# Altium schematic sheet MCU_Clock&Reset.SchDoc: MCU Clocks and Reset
size A4; Date: Not used; ApprovedBy: Not used; CheckedBy: Not used; Author: Not used; CompanyName: STMicroelectronics; DrawnBy: Not used; Engineer: Not used; Organization: Not used; Address1: Not used; Address2: Not used; Address3: Not used; Address4: Not used; DocumentNumber: Not used; Revision: Not used; SheetNumber: 4; SheetTotal: 23
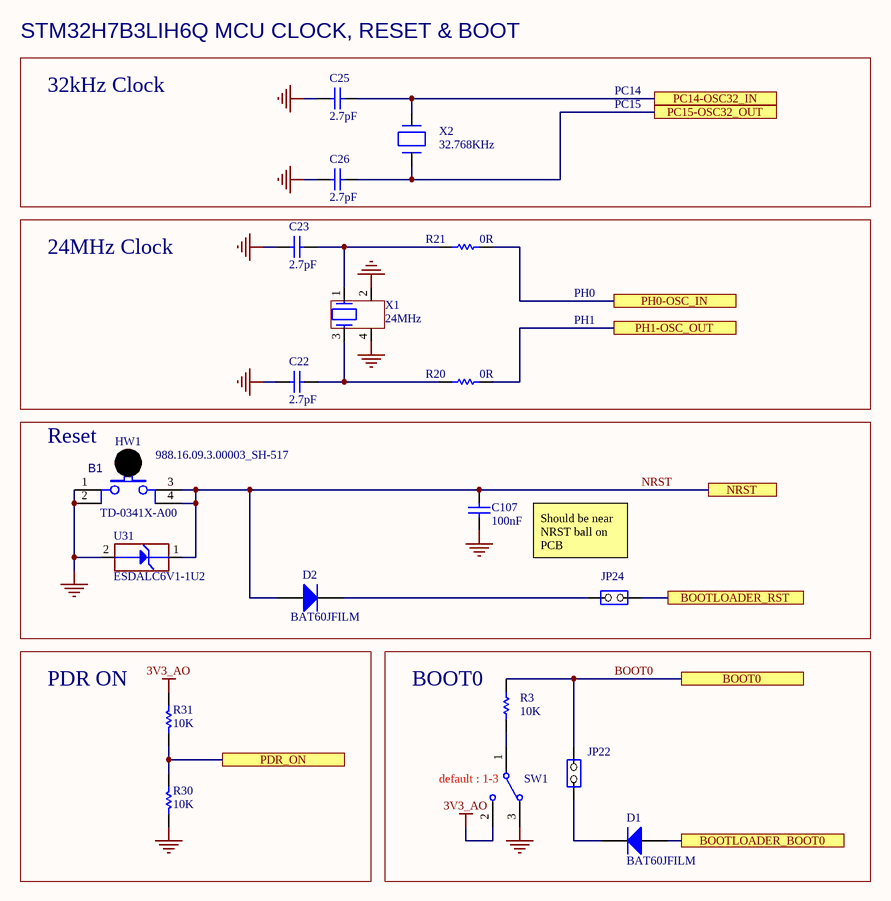
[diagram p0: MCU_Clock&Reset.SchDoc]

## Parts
B1  value TD-0341X-A00  [SWI_WEALTHMETAL_TD-0341_4P_BLACK]  (hidden comment: SW-PUSH-CMS)
C22  value 2.7pF  [C0603]  (hidden comment: Capacitor)
C23  value 2.7pF  [C0603]  (hidden comment: Capacitor)
C25  value 2.7pF  [C0603]  (hidden comment: Capacitor)
C26  value 2.7pF  [C0603]  (hidden comment: Capacitor)
C107  value 100nF  [C0402]  (hidden comment: Capacitor)
D1  BAT60JFILM  [DIO_SOD323]
D2  BAT60JFILM  [DIO_SOD323]
HW1  value 988.16.09.3.00003_SH-517  (hidden comment: BUTTON_HAT_BLACK)  (mechanical)
JP22  Jumper_Header 2x1  [CON_SAMTEC_TSW-102-07-G-S]  (value not drawn)
JP24  Jumper_Header 2x1  [CON_SAMTEC_TSW-102-07-G-S]  (value not drawn)
R3  value 10K  [R0402]  (hidden comment: Resistor)
R20  value 0R  [R0402]  (hidden comment: Resistor)
R21  value 0R  [R0402]  (hidden comment: Resistor)
R30  value 10K  [R0402]  (hidden comment: Resistor)
R31  value 10K  [R0402]  (hidden comment: Resistor)
SW1  SW_MECA_1K2  [SWI_EAO_09-03290-01_EXTENDED_STRAIGHT_BLACK]  (value not drawn)
U31  value ESDALC6V1-1U2  [ESD_ST0201]  (hidden comment: ESD-TRANSIL)
X1  value 24MHz  [CRY_NX2016SA_4P]  (hidden comment: XTAL_4_PINS)
X2  value 32.768KHz  [CRY_NX3215SA_2P]  (hidden comment: XTAL_2_PINS)

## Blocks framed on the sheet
24MHz Clock: C22 C23 R20 R21 X1
Reset: B1 C107 D2 HW1 JP24 U31
PDR ON: R30 R31
BOOT0: D1 JP22 R3 SW1

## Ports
BOOT0, BOOTLOADER_BOOT0, BOOTLOADER_RST, NRST, PC14-OSC32_IN, PC15-OSC32_OUT, PDR_ON, PH0-OSC_IN, PH1-OSC_OUT

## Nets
3V3_AO: R31.1 SW1.2
GND: B1.1 B1.2 C22.1 C23.1 C25.1 C26.1 C107.1 R30.2 SW1.3 U31.2(GND) X1.2 X1.4
BOOT0: JP22.2(NO) R3.1 ; port BOOT0
BOOTLOADER_BOOT0: D1.1(A) ; port BOOTLOADER_BOOT0
BOOTLOADER_RST: JP24.2(NO) ; port BOOTLOADER_RST
NRST: B1.3 B1.4 C107.2 D2.1(A) U31.1(IO1) ; port NRST
PC14-OSC32_IN: C25.2 X2.2(X2) ; port PC14-OSC32_IN
PC15-OSC32_OUT: C26.2 X2.1(X1) ; port PC15-OSC32_OUT
PDR_ON: R30.1 R31.2 ; port PDR_ON
PH0-OSC_IN: R21.2 ; port PH0-OSC_IN
PH1-OSC_OUT: R20.2 ; port PH1-OSC_OUT
NetC22_2: C22.2 R20.1 X1.3
NetC23_2: C23.2 R21.1 X1.1
NetD1_2: D1.2(K) JP22.1(COMMON)
NetD2_2: D2.2(K) JP24.1(COMMON)
NetR3_2: R3.2 SW1.1

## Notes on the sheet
- STM32H7B3LIH6Q MCU CLOCK, RESET & BOOT
- 32kHz Clock
- PC14
- PC15
- PH0
- PH1
- Should be near NRST ball on PCB
- (near SW1) default : 1-3

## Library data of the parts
B1 = MCD-00001: Non-Open Push-Button 0.1A 24V BLACK; Manufacturer: WEALTHMETAL; Part_Type: Misc; Part_Preference: Not recommended; Partial_Alternate_Internal_Part_Number: MCD-03587; Provided_By: SUBCO; Alternate_EMS: A; Component_Country_Of_Origin: Unknown; ID: 2463; ShowFields: YES
C22 C23 C25 C26 = MCD-01726: Capacitor, MLCC, 2.7pF, 50V, NPO, -+0.25pF 0603; Manufacturer_Part_Number: CC0603CRNPO9BN2R7; Manufacturer: YAGEO; Part_Preference: Recommended; Provided_By: SUBCO; Component_Country_Of_Origin: China; ID: 3826; Order_Code_RS: 616-9155; ShowFields: YES
C107 = MCD-00006: Capacitor, MLCC, 100nF, 16V, X7R, 10%, 0402, T=0.5mm; Manufacturer_Part_Number: CC0402KRX7R7BB104; Manufacturer: YAGEO; Alternate_Manufacturer_Part_Number: GCM155R71C104KA55D; Alternate_Manufacturer: MURATA; Part_Preference: Recommended; Partial_Alternate_Internal_Part_Number: MCD-03299; Provided_By: SUBCO; ECCN_US: EAR99; ECCN_EU: NEC; Component_Country_Of_Origin: China; ID: 2474; Order_Code_RS: 9402047; ShowFields: YES
D1 D2 = MCD-00034: Manufacturer: STMICROELECTRONICS; Part_Type: Diode; BMS_Part_Number: 9151097; Manufacturer_HQ_COO: EU; Part_Preference: Recommended; Provided_By: SUBCO with ST control; ECCN_US: EAR99; ECCN_EU: NEC; Component_Country_Of_Origin: China; ID: 2483; Order_Code_RS: 714-6879; ShowFields: YES
HW1 = MCD-00635: Black Hat for switch TD0341X-G01-BLA; Part_Type: Mechanical; Manufacturer: JIUBABA; Part_Preference: Alternate; Provided_By: SUBCO; Alternate_EMS: A; Component_Country_Of_Origin: Unknown; ID: 3106; ShowFields: YES
JP22 JP24 = MCD-00045: Header, 2x1, 2,54mm, VR, TH, Height 5.84mm/2.54mm; Manufacturer_Part_Number: TSW-102-07-G-S; Manufacturer: SAMTEC; Part_Type: Connector; Alternate_Manufacturer_Part_Number: 313102S111116;313102S111116; Alternate_Manufacturer: JIUBABA; LIANYI; Full_Alternate_Internal_Part_Number: MCD-02390; Part_Preference: Recommended; Partial_Alternate_Internal_Part_Number: MCD-02957, MCD-03720; Provided_By: SUBCO; Component_Country_Of_Origin: China, Costa Rica, Malaysia, USA, Vietnam; ID: 2545; Order_Code_RS: 2505044; ShowFields: YES
R3 R30 R31 = MCD-00053: Resistor,10K,0402,1%,1/16W; Manufacturer_Part_Number: RC0402FR-0710KL; Manufacturer: YAGEO; BMS_Part_Number: 9131590; Part_Preference: Recommended; Provided_By: SUBCO; ECCN_US: EAR99; ECCN_EU: NEC; Component_Country_Of_Origin: China; ID: 2539; Order_Code_RS: 9239359; ShowFields: YES
R20 R21 = MCD-00052: Resistor,0R,0402,5%,1/16W; Manufacturer_Part_Number: RC0402JR-070RL; Manufacturer: YAGEO; Part_Preference: Recommended; Provided_By: SUBCO; ECCN_US: EAR99; ECCN_EU: NEC; Component_Country_Of_Origin: China; ID: 2540; Order_Code_RS: 9232516RL; ShowFields: YES
SW1 = MCD-00566: Mechanical Slide Switches 1K2 BLK ACT GOLD STRT MNT; Part_Type: Misc; Manufacturer: EAO; Part_Preference: Recommended; Value: 09.03290.01; Provided_By: SUBCO; Component_Country_Of_Origin: Switzerland°°; ID: 3181; Order_Code_RS: 204-7865; ShowFields: YES
U31 = MCD-00170: ESD protection 6V1; Part_Type: Diode; Manufacturer: STMICROELECTRONICS; BMS_Part_Number: 9151132; Manufacturer_HQ_COO: EU; Part_Preference: Recommended; Provided_By: SUBCO with ST control; ECCN_US: EAR99; ECCN_EU: NEC; Component_Country_Of_Origin: China; ID: 2696; Order_Code_RS: 795-8404; ShowFields: YES
X1 = MCD-01036: Crystal 24MHz, 6pF, +-20ppm, 80ohms max, SMD; Part_Type: Crystal_Osc; Manufacturer_Part_Number: NX2016SA-24MHZ-EXS00A-CS10820; Manufacturer: NDK; BMS_Part_Number: 9157045; Part_Preference: Recommended; Provided_By: SUBCO; ECCN_US: EAR99; ECCN_EU: NEC; Component_Country_Of_Origin: Unknown; ID: 2989; ShowFields: YES
X2 = MCD-00091: Crystal 32.768kHz, 6pF, +-20ppm, 50Kohms max, SMD; Part_Type: Crystal_Osc; Manufacturer_Part_Number: NX3215SA-32.768KHZ-EXS00A-MU00525; Manufacturer: NDK; BMS_Part_Number: 9157034; Part_Preference: Recommended; Provided_By: SUBCO; ECCN_US: EAR99; ECCN_EU: NEC; Component_Country_Of_Origin: Unknown; ID: 2553; ShowFields: YES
